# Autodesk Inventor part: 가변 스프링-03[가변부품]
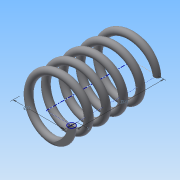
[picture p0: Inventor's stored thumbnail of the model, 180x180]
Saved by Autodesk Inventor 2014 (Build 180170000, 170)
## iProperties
Created: 2015-09
Part Number: 가변 스프링-03[가변부품]
Material: 강철, 탄소
Document SubType Name: Modeling
Designer: study
Density: 1 g/cm^3
Appearance: 반연마
Author: study
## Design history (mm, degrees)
sketch "스케치1"
  geometry: L1 (0, 0)-(11, 0); L2 (11, 0)-(11, 36.411); L3 (11, 36.411)-(0, 36.411); L4 (0, 36.411)-(0, 0); C1 r 1.5 at (11, 0)
  constraints: 8 end point, 2 parallel, 1 centre point, 1 coincident, 1 horizontal, 1 perpendicular
  dimensions: "d0" = 3 diameter of C1; "d1" = 22 diameter of L2 L4; "d2" = 36.4112 distance of L1.end L2.end (derived)
feature "코일1" sketch "스케치1" pitch "d3" = 10; turns "d5" = 5; dims "d4" = 36.4112 (= d2), "d6" = 0, angle "d7" = 90 deg, angle "d8" = 90 deg, "d9" = 0, "d10" = 0
node "작업 평면1"
sketch "스케치2"
  geometry: L1 (-12.5, 0)-(-9.5, 0) reference; 1 further point
  constraints: 1 horizontal alignment
extrude "돌출1" cut sketch "스케치2" distance "d12" = 10; taper "d13" = 0 deg
node "작업 평면2"
sketch "스케치3"
  geometry: L1 (-9.5, 0)-(-12.5, 0) reference; L2 (-9.5, 0)-(-12.5, 0) reference; 1 further point
  constraints: 2 horizontal alignment
extrude "돌출2" cut sketch "스케치3" distance "d15" = 10; taper "d16" = 0 deg
node "솔리드1"
node "절단 모서리 투영1"
node "절단 모서리 투영2"
node "절단 모서리 투영3"
other parameters: "d11" = 0, "d14" = 36.4112 (= d2)
